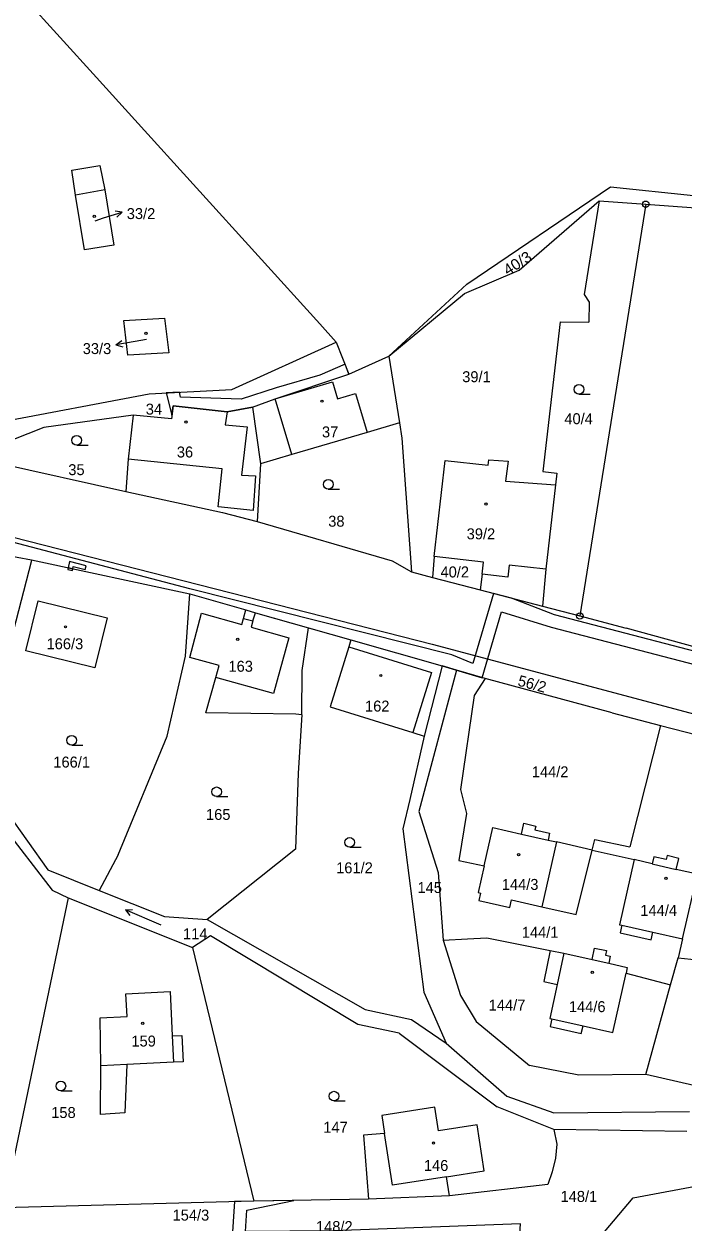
# Model space of a CAD drawing. Extents: x -727701 to -724405, y -960481 to -957284.
# Drawn here: x -726630.1 to -726527.9, y -958207.9 to -958022 of the extents above; entities that cross this region are included whole.
import ezdxf
from ezdxf.enums import TextEntityAlignment as Align

# ---------------------------------------------------------------- set-up
doc = ezdxf.new("R2010")
doc.units = 0
doc.header["$LTSCALE"] = 0.68
for name, color, linetype, lineweight in [('1', 7, 'Continuous', 25), ('13', 7, 'Continuous', 13), ('3', 7, 'Continuous', 25), ('4', 7, 'Continuous', 13), ('5', 7, 'Continuous', 25), ('7', 7, 'Continuous', 13), ('8', 7, 'Continuous', 25)]:
    doc.layers.add(name, color=color, linetype=linetype, lineweight=lineweight)
doc.layers.add('2', color=7, linetype='Continuous')

msp = doc.modelspace()

# ---------------------------------------------------------------- linework, layer by layer
at = {"layer": '1'}
for p, q in [((-726634.18, -958013.37), (-726618.86, -958030.28)), ((-726618.86, -958030.28), (-726612.93, -958036.83)), ((-726612.93, -958036.83), (-726584.21, -958068.52)), ((-726622.71, -958044.65), (-726618.34, -958043.92)), ((-726622.15, -958048.51), (-726622.71, -958044.65)), ((-726618.34, -958043.92), (-726617.58, -958047.72)), ((-726561.41, -958062.33), (-726539.1, -958047.26)), ((-726620.75, -958057.02), (-726622.15, -958048.51)), ((-726617.58, -958047.72), (-726616.18, -958056.3)), ((-726553.27, -958060.18), (-726540.9, -958049.4)), ((-726533.66, -958049.94), (-726543.88, -958113.84)), ((-726540.9, -958049.4), (-726543.21, -958063.93)), ((-726540.9, -958049.4), (-726533.66, -958049.94)), ((-726533.66, -958049.94), (-726525.88, -958050.52)), ((-726616.18, -958056.3), (-726620.75, -958057.02)), ((-726561.79, -958063.8), (-726553.27, -958060.18)), ((-726561.41, -958062.33), (-726573.5, -958073.5)), ((-726573.5, -958073.5), (-726561.79, -958063.8)), ((-726543.21, -958063.93), (-726542.42, -958065.13)), ((-726542.42, -958065.13), (-726542.46, -958068.26)), ((-726614.66, -958067.99), (-726608.33, -958067.64)), ((-726608.33, -958067.64), (-726607.67, -958072.99)), ((-726613.99, -958073.35), (-726614.66, -958067.99)), ((-726581.67, -958071.32), (-726584.21, -958068.52)), ((-726546.92, -958068.2), (-726549.6, -958091.43)), ((-726546.92, -958068.2), (-726542.46, -958068.26)), ((-726597.9, -958078.71), (-726581.67, -958071.32)), ((-726581.67, -958071.32), (-726579.7, -958076.29)), ((-726607.67, -958072.99), (-726613.99, -958073.35)), ((-726579.7, -958076.29), (-726573.5, -958073.5)), ((-726573.5, -958073.5), (-726571.87, -958083.85)), ((-726591.14, -958080.14), (-726579.7, -958076.29)), ((-726610.68, -958079.34), (-726597.9, -958078.71)), ((-726639.17, -958084.77), (-726610.68, -958079.34)), ((-726594.65, -958081.43), (-726591.14, -958080.14)), ((-726613.2, -958082.65), (-726627.07, -958084.61)), ((-726613.2, -958082.65), (-726613.95, -958089.5)), ((-726607.25, -958083.25), (-726613.2, -958082.65)), ((-726607, -958081.25), (-726607.25, -958083.25)), ((-726598.6, -958082.15), (-726607, -958081.25)), ((-726594.65, -958081.43), (-726598.6, -958082.15)), ((-726594.65, -958081.43), (-726593.44, -958090.24)), ((-726571.87, -958083.85), (-726576.9, -958085.34)), ((-726571.87, -958083.85), (-726571.5, -958086.22)), ((-726627.07, -958084.61), (-726638.52, -958089.14)), ((-726576.9, -958085.34), (-726588.57, -958088.8)), ((-726571.5, -958086.22), (-726570, -958107)), ((-726638.52, -958089.14), (-726614.35, -958094.5)), ((-726613.95, -958089.5), (-726614.35, -958094.5)), ((-726588.57, -958088.8), (-726593.44, -958090.24)), ((-726566.5, -958104.6), (-726564.78, -958089.69)), ((-726564.78, -958089.69), (-726558.08, -958090.42)), ((-726558.08, -958090.42), (-726558, -958089.59)), ((-726558, -958089.59), (-726554.99, -958089.84)), ((-726554.99, -958089.84), (-726555.43, -958092.9)), ((-726593.44, -958090.24), (-726593.95, -958099.2)), ((-726549.6, -958091.43), (-726547.46, -958091.68)), ((-726547.46, -958091.68), (-726547.67, -958093.49)), ((-726555.43, -958092.9), (-726547.67, -958093.49)), ((-726547.67, -958093.49), (-726549.17, -958106.58)), ((-726614.35, -958094.5), (-726599.34, -958097.76)), ((-726599.34, -958097.76), (-726593.95, -958099.2)), ((-726593.95, -958099.2), (-726573, -958105.3)), ((-726634.4, -958100.95), (-726566.79, -958118.23)), ((-726633.4, -958104.3), (-726628.95, -958105.15)), ((-726566.5, -958104.6), (-726566.76, -958107.85)), ((-726558.84, -958105.47), (-726566.5, -958104.6)), ((-726628.97, -958105.23), (-726638.69, -958142.79)), ((-726628.95, -958105.15), (-726628.97, -958105.23)), ((-726628.95, -958105.15), (-726604.4, -958110.4)), ((-726573, -958105.3), (-726570, -958107)), ((-726559.06, -958107.36), (-726558.84, -958105.47)), ((-726549.17, -958106.58), (-726549.68, -958112.32)), ((-726570, -958107), (-726566.76, -958107.85)), ((-726566.76, -958107.85), (-726559.35, -958109.79)), ((-726559.06, -958107.36), (-726559.35, -958109.79)), ((-726605.08, -958120.09), (-726604.4, -958110.4)), ((-726604.4, -958110.4), (-726595.69, -958112.91)), ((-726559.35, -958109.79), (-726549.68, -958112.32)), ((-726629.83, -958119.25), (-726627.92, -958111.47)), ((-726627.92, -958111.47), (-726617.22, -958114.13)), ((-726549.68, -958112.32), (-726543.88, -958113.84)), ((-726617.22, -958114.13), (-726619.13, -958121.9)), ((-726604.41, -958120.28), (-726602.58, -958113.43)), ((-726602.58, -958113.43), (-726596.32, -958115.17)), ((-726596.32, -958115.17), (-726596.06, -958114.21)), ((-726596.06, -958114.21), (-726595.69, -958112.91)), ((-726595.69, -958112.91), (-726594.22, -958113.33)), ((-726594.22, -958113.33), (-726586, -958115.7)), ((-726543.88, -958113.84), (-726536.67, -958115.73)), ((-726586.95, -958122.3), (-726586, -958115.7)), ((-726586, -958115.7), (-726579.4, -958117.55)), ((-726492.36, -958127.89), (-726536.67, -958115.73)), ((-726579.4, -958117.55), (-726579.74, -958118.63)), ((-726579.4, -958117.55), (-726565.25, -958121.6)), ((-726619.13, -958121.9), (-726629.83, -958119.25)), ((-726579.74, -958118.63), (-726582.63, -958127.95)), ((-726566.79, -958118.23), (-726443.24, -958151.08)), ((-726607.9, -958132.5), (-726605.08, -958120.09)), ((-726599.86, -958121.55), (-726604.41, -958120.28)), ((-726600.37, -958123.38), (-726599.86, -958121.55)), ((-726565.25, -958121.6), (-726568.02, -958132.48)), ((-726563.01, -958122.26), (-726565.25, -958121.6)), ((-726601.9, -958128.87), (-726600.37, -958123.38)), ((-726587, -958129.2), (-726586.95, -958122.3)), ((-726563.01, -958122.26), (-726568.87, -958144.2)), ((-726558.57, -958123.57), (-726563.01, -958122.26)), ((-726558.57, -958123.57), (-726560.3, -958126.2)), ((-726538.86, -958128.86), (-726558.57, -958123.57)), ((-726560.3, -958126.2), (-726562.42, -958140.75)), ((-726587.95, -958129.08), (-726601.9, -958128.87)), ((-726587, -958129.2), (-726587.95, -958129.08)), ((-726582.63, -958127.95), (-726569.78, -958131.93)), ((-726538.86, -958128.86), (-726531.37, -958130.82)), ((-726587, -958129.2), (-726587.59, -958138.22)), ((-726531.37, -958130.82), (-726536.12, -958149.69)), ((-726531.37, -958130.82), (-726501.37, -958138.64)), ((-726615.5, -958150.9), (-726607.9, -958132.5)), ((-726568.02, -958132.48), (-726570.27, -958142.33)), ((-726569.78, -958131.93), (-726568.02, -958132.48)), ((-726587.59, -958138.22), (-726588.02, -958150.01)), ((-726562.42, -958140.75), (-726561.47, -958144.52)), ((-726570.27, -958142.33), (-726571.34, -958146.9)), ((-726632.73, -958144.34), (-726626.43, -958153.22)), ((-726568.87, -958144.2), (-726565.85, -958153.67)), ((-726561.47, -958144.52), (-726562.67, -958151.79)), ((-726633.59, -958146.25), (-726625.75, -958156.4)), ((-726571.34, -958146.9), (-726568.09, -958172.24)), ((-726558.7, -958152.6), (-726557.36, -958146.69)), ((-726557.36, -958146.69), (-726552.92, -958147.69)), ((-726552.92, -958147.69), (-726552.55, -958146.02)), ((-726552.55, -958146.02), (-726550.72, -958146.48)), ((-726550.72, -958146.48), (-726550.84, -958147.03)), ((-726550.84, -958147.03), (-726548.57, -958147.54)), ((-726548.57, -958147.54), (-726548.81, -958148.62)), ((-726548.81, -958148.62), (-726547.49, -958148.91)), ((-726541.97, -958150.18), (-726547.49, -958148.91)), ((-726541.97, -958150.18), (-726541.53, -958148.52)), ((-726541.53, -958148.52), (-726536.12, -958149.69)), ((-726615.5, -958150.9), (-726618.45, -958156.43)), ((-726588.02, -958150.01), (-726601.69, -958160.96)), ((-726544.46, -958160.19), (-726541.97, -958150.18)), ((-726541.97, -958150.18), (-726535.47, -958151.66)), ((-726532.41, -958151.23), (-726532.66, -958152.31)), ((-726530.49, -958151.64), (-726532.41, -958151.23)), ((-726530.35, -958151.04), (-726530.49, -958151.64)), ((-726528.52, -958151.46), (-726530.35, -958151.04)), ((-726528.91, -958153.17), (-726528.52, -958151.46)), ((-726626.43, -958153.22), (-726618.45, -958156.43)), ((-726562.67, -958151.79), (-726558.7, -958152.6)), ((-726558.7, -958152.6), (-726559.64, -958156.77)), ((-726535.47, -958151.66), (-726537.71, -958161.76)), ((-726532.66, -958152.31), (-726535.47, -958151.66)), ((-726525.61, -958153.92), (-726528.91, -958153.17)), ((-726565.85, -958153.67), (-726565.08, -958164.18)), ((-726527.94, -958163.96), (-726525.61, -958153.92)), ((-726625.75, -958156.4), (-726623.26, -958157.59)), ((-726618.45, -958156.43), (-726608.34, -958160.5)), ((-726559.64, -958156.77), (-726559.3, -958156.85)), ((-726559.3, -958156.85), (-726559.56, -958158.02)), ((-726623.26, -958157.59), (-726633.29, -958205.71)), ((-726623.26, -958157.59), (-726604, -958165.3)), ((-726559.56, -958158.02), (-726554.76, -958159.09)), ((-726554.76, -958159.09), (-726554.5, -958157.92)), ((-726554.5, -958157.92), (-726549.78, -958158.98)), ((-726608.34, -958160.5), (-726601.69, -958160.96)), ((-726549.78, -958158.98), (-726544.46, -958160.19)), ((-726601.69, -958160.96), (-726577.2, -958174.91)), ((-726537.71, -958161.76), (-726537.39, -958161.83)), ((-726537.39, -958161.83), (-726537.65, -958163)), ((-726601.18, -958163.48), (-726604, -958165.3)), ((-726578.31, -958177.24), (-726601.18, -958163.48)), ((-726565.08, -958164.18), (-726561.29, -958163.96)), ((-726565.08, -958164.18), (-726562.42, -958172.76)), ((-726561.29, -958163.96), (-726558.3, -958163.79)), ((-726558.3, -958163.79), (-726548.47, -958165.76)), ((-726537.65, -958163), (-726532.82, -958164.09)), ((-726532.82, -958164.09), (-726532.56, -958162.92)), ((-726532.56, -958162.92), (-726527.94, -958163.96)), ((-726527.94, -958163.96), (-726528.64, -958166.9)), ((-726604, -958165.3), (-726594.48, -958204.65)), ((-726548.47, -958165.76), (-726549.47, -958170.59)), ((-726548.47, -958165.76), (-726546.37, -958166.18)), ((-726546.37, -958166.18), (-726541.98, -958167.16)), ((-726541.98, -958167.16), (-726541.59, -958165.4)), ((-726541.59, -958165.4), (-726539.74, -958165.74)), ((-726539.74, -958165.74), (-726539.91, -958166.49)), ((-726539.91, -958166.49), (-726539.15, -958166.66)), ((-726539.15, -958166.66), (-726539.39, -958167.74)), ((-726539.39, -958167.74), (-726536.52, -958168.39)), ((-726529.79, -958171.09), (-726528.64, -958166.9)), ((-726528.64, -958166.9), (-726508.31, -958169.06)), ((-726538.77, -958178.46), (-726536.71, -958169.26)), ((-726536.52, -958168.39), (-726536.71, -958169.26)), ((-726536.71, -958169.26), (-726529.79, -958171.09)), ((-726549.47, -958170.59), (-726547.42, -958171.01)), ((-726547.42, -958171.01), (-726548.56, -958176.3)), ((-726533.62, -958184.99), (-726529.79, -958171.09)), ((-726614.3, -958172.47), (-726607.45, -958172.13)), ((-726614.12, -958176.01), (-726614.3, -958172.47)), ((-726607.45, -958172.13), (-726607.11, -958179.01)), ((-726568.09, -958172.24), (-726564.61, -958180.15)), ((-726562.42, -958172.76), (-726559.95, -958176.78)), ((-726577.2, -958174.91), (-726569.99, -958176.49)), ((-726618.32, -958176.21), (-726614.12, -958176.01)), ((-726618.21, -958183.67), (-726618.32, -958176.21)), ((-726571.9, -958178.57), (-726578.31, -958177.24)), ((-726569.99, -958176.49), (-726564.61, -958180.15)), ((-726559.95, -958176.78), (-726551.71, -958183.62)), ((-726548.56, -958176.3), (-726548.22, -958176.38)), ((-726548.22, -958176.38), (-726548.48, -958177.55)), ((-726543.65, -958178.62), (-726543.39, -958177.44)), ((-726543.39, -958177.44), (-726538.77, -958178.46)), ((-726607.11, -958179.01), (-726605.61, -958178.94)), ((-726605.61, -958178.94), (-726605.41, -958183.04)), ((-726571.9, -958178.57), (-726556.73, -958190.04)), ((-726548.48, -958177.55), (-726543.65, -958178.62)), ((-726564.61, -958180.15), (-726555.22, -958188.35)), ((-726605.41, -958183.04), (-726606.91, -958183.11)), ((-726618.24, -958191.21), (-726618.21, -958183.67)), ((-726614.15, -958183.47), (-726614.46, -958190.94)), ((-726606.91, -958183.11), (-726614.15, -958183.47)), ((-726544.02, -958185.11), (-726551.71, -958183.62)), ((-726533.62, -958184.99), (-726544.02, -958185.11)), ((-726513.25, -958189.75), (-726533.62, -958184.99)), ((-726555.22, -958188.35), (-726547.93, -958190.97)), ((-726566.36, -958190.07), (-726574.62, -958191.36)), ((-726565.79, -958193.75), (-726566.36, -958190.07)), ((-726547.92, -958193.53), (-726556.73, -958190.04)), ((-726614.46, -958190.94), (-726618.24, -958191.21)), ((-726574.62, -958191.36), (-726574.18, -958194.18)), ((-726547.93, -958190.97), (-726526.87, -958190.73)), ((-726574.18, -958194.18), (-726577.45, -958194.43)), ((-726559.81, -958192.82), (-726565.79, -958193.75)), ((-726558.7, -958199.97), (-726559.81, -958192.82)), ((-726527.26, -958193.85), (-726547.92, -958193.53)), ((-726547.92, -958193.53), (-726547.44, -958195.8)), ((-726577.45, -958194.43), (-726576.69, -958204.35)), ((-726547.44, -958195.8), (-726547.68, -958197.99)), ((-726547.68, -958197.99), (-726548.17, -958200.1)), ((-726564.58, -958200.88), (-726558.7, -958199.97)), ((-726564.13, -958203.82), (-726564.58, -958200.88)), ((-726548.17, -958200.1), (-726548.85, -958202.09)), ((-726548.85, -958202.09), (-726564.13, -958203.82)), ((-726535.63, -958204.12), (-726524.27, -958202)), ((-726594.48, -958204.65), (-726633.29, -958205.71)), ((-726576.69, -958204.35), (-726594.48, -958204.65)), ((-726564.13, -958203.82), (-726576.69, -958204.35)), ((-726544.56, -958214.79), (-726535.63, -958204.12))]:
    msp.add_line(p, q, dxfattribs=at)
msp.add_lwpolyline([(-726539.1, -958047.26), (-726526.27, -958048.56), (-726525.88, -958050.52), (-726524.67, -958051.03)], dxfattribs=at)
at = {"layer": '13'}
for points in [[(-726580.31, -958074.76), (-726584.24, -958076.45), (-726591.01, -958078.41), (-726596.45, -958080.2), (-726605.82, -958079.88), (-726606.02, -958079.11), (-726608.05, -958079.21), (-726607.18, -958082.69), (-726607, -958081.25), (-726598.6, -958082.15), (-726594.65, -958081.43), (-726591.14, -958080.14), (-726579.7, -958076.29)], [(-726623.3, -958106.61), (-726622.62, -958106.76), (-726622.56, -958106.52), (-726623.25, -958106.37)], [(-726623.25, -958106.37), (-726622.56, -958106.52), (-726622.48, -958106.17), (-726620.65, -958106.63), (-726620.5, -958106.05), (-726623.04, -958105.41)], [(-726594.48, -958204.65), (-726597.46, -958204.73), (-726597.89, -958210.97), (-726587.7, -958210.7), (-726587.45, -958211.3), (-726583.72, -958211.27), (-726580.73, -958213.13), (-726579.4, -958213.15), (-726579.42, -958211.16), (-726555.25, -958210.25), (-726555.32, -958211.34), (-726553.3, -958211.15), (-726553.11, -958208.16), (-726582.05, -958209.26), (-726595.78, -958209.36), (-726595.55, -958206.05), (-726588.27, -958204.55)]]:
    msp.add_lwpolyline(points, close=True, dxfattribs=at)
for points in [[(-726486.7, -958129.58), (-726547.8, -958113.68), (-726554.49, -958111.06), (-726557.27, -958110.33), (-726560.49, -958121.2), (-726563.75, -958119.85), (-726604.4, -958109.65), (-726644.73, -958099.04)], [(-726633.4, -958104.3), (-726628.95, -958105.15), (-726604.4, -958110.4), (-726595.69, -958112.91), (-726594.22, -958113.33), (-726579.4, -958117.55), (-726565.25, -958121.6), (-726559.06, -958123.43), (-726556.03, -958113.19), (-726548.35, -958115.6), (-726487.36, -958131.48)]]:
    msp.add_lwpolyline(points, dxfattribs=at)
at = {"layer": '3'}
for p, q in [((-726544.013, -958079.42), (-726542.263, -958079.42)), ((-726621.943, -958087.33), (-726620.193, -958087.33)), ((-726582.913, -958094.16), (-726581.163, -958094.16)), ((-726622.723, -958133.88), (-726620.973, -958133.88)), ((-726600.233, -958141.88), (-726598.483, -958141.88)), ((-726579.583, -958149.74), (-726577.833, -958149.74)), ((-726614.384, -958159.473), (-726613.289, -958159.393)), ((-726624.403, -958187.54), (-726622.653, -958187.54)), ((-726582.033, -958189.11), (-726580.283, -958189.11))]:
    msp.add_line(p, q, dxfattribs=at)
msp.add_lwpolyline([(-726608.861, -958161.818), (-726614.384, -958159.473), (-726613.68, -958160.317)], dxfattribs=at)
for centre in [(-726544.0129, -958078.6698), (-726621.9429, -958086.5798), (-726582.9129, -958093.4098), (-726622.7229, -958133.1298), (-726600.2329, -958141.1298), (-726579.5829, -958148.9898), (-726624.4029, -958186.7898), (-726582.0329, -958188.3598)]:
    msp.add_circle(centre, 0.75, dxfattribs=at)
at = {"layer": '4'}
for p, q in [((-726617.58, -958047.72), (-726622.15, -958048.51)), ((-726591.14, -958080.14), (-726582.25, -958077.51)), ((-726582.25, -958077.51), (-726581.46, -958080.16)), ((-726588.57, -958088.8), (-726591.14, -958080.14)), ((-726581.46, -958080.16), (-726578.68, -958079.33)), ((-726578.68, -958079.33), (-726576.9, -958085.34)), ((-726598.6, -958082.15), (-726598.9, -958084.15)), ((-726598.9, -958084.15), (-726595.5, -958084.5)), ((-726595.5, -958084.5), (-726596.4, -958092)), ((-726599.4, -958091), (-726613.95, -958089.5)), ((-726600, -958096.9), (-726599.4, -958091)), ((-726596.4, -958092), (-726594.22, -958092.1)), ((-726594.22, -958092.1), (-726594.55, -958097.45)), ((-726594.55, -958097.45), (-726600, -958096.9)), ((-726554.84, -958105.93), (-726555.05, -958107.82)), ((-726549.17, -958106.58), (-726554.84, -958105.93)), ((-726555.05, -958107.82), (-726559.06, -958107.36)), ((-726596.06, -958114.21), (-726594.61, -958114.61)), ((-726594.61, -958114.61), (-726594.22, -958113.33)), ((-726594.61, -958114.61), (-726594.88, -958115.57)), ((-726594.88, -958115.57), (-726589.01, -958117.21)), ((-726589.01, -958117.21), (-726591.42, -958125.87)), ((-726579.74, -958118.63), (-726566.89, -958122.62)), ((-726591.42, -958125.87), (-726600.37, -958123.38)), ((-726566.89, -958122.62), (-726569.78, -958131.93)), ((-726552.92, -958147.69), (-726548.81, -958148.62)), ((-726547.49, -958148.91), (-726549.78, -958158.98)), ((-726532.66, -958152.31), (-726528.91, -958153.17)), ((-726537.39, -958161.83), (-726532.56, -958162.92)), ((-726546.37, -958166.18), (-726547.42, -958171.01)), ((-726541.98, -958167.16), (-726539.39, -958167.74)), ((-726548.22, -958176.38), (-726543.39, -958177.44)), ((-726607.11, -958179.01), (-726606.91, -958183.11)), ((-726614.15, -958183.47), (-726618.21, -958183.67)), ((-726572.94, -958202.18), (-726574.18, -958194.18)), ((-726564.58, -958200.88), (-726572.94, -958202.18))]:
    msp.add_line(p, q, dxfattribs=at)
at = {"layer": '5'}
for centre in [(-726619.2268, -958051.8292), (-726611.2068, -958069.9692), (-726583.8968, -958080.4992), (-726605.0068, -958083.7392), (-726558.4468, -958096.4692), (-726623.6868, -958115.5292), (-726596.9668, -958117.4492), (-726574.7568, -958123.0792), (-726553.3868, -958150.8692), (-726530.5168, -958154.5492), (-726541.9568, -958169.1592), (-726611.6968, -958177.0692), (-726566.5868, -958195.6392)]:
    msp.add_circle(centre, 0.175, dxfattribs=at)
at = {"layer": '7'}
for p, q in [((-726614.9, -958051.193), (-726616.004, -958051.007)), ((-726615.855, -958071.771), (-726614.782, -958072.09))]:
    msp.add_line(p, q, dxfattribs=at)
for points in [[(-726619.1, -958052.49), (-726617.77, -958052.07), (-726614.9, -958051.193), (-726615.711, -958051.964)], [(-726611.1, -958070.92), (-726612.9, -958071.25), (-726615.855, -958071.771), (-726614.956, -958071.104)]]:
    msp.add_lwpolyline(points, dxfattribs=at)
at = {"layer": '8'}
for centre, radius in [((-726533.66, -958049.9399), 0.5), ((-726533.66, -958049.9399), 0.0303), ((-726543.88, -958113.8399), 0.5), ((-726543.88, -958113.8399), 0.0303)]:
    msp.add_circle(centre, radius, dxfattribs=at)

# ---------------------------------------------------------------- texts
at = {"layer": '2'}
for s, p in [('33/2', (-726614.18, -958052.242)), ('34', (-726611.23, -958082.585)), ('37', (-726583.89, -958086.125)), ('36', (-726606.41, -958089.245)), ('35', (-726623.25, -958091.985)), ('38', (-726582.92, -958099.985)), ('39/2', (-726561.44, -958101.945)), ('40/2', (-726565.5, -958107.855)), ('163', (-726598.4, -958122.495)), ('162', (-726577.21, -958128.675)), ('165', (-726601.88, -958145.495)), ('161/2', (-726581.69, -958153.775)), ('145', (-726569.07, -958156.835)), ('144/3', (-726555.99, -958156.355)), ('144/4', (-726534.49, -958160.385)), ('114', (-726605.45, -958164.015)), ('144/6', (-726545.58, -958175.325)), ('159', (-726613.46, -958180.665)), ('158', (-726625.9, -958191.755)), ('147', (-726583.68, -958194.035)), ('146', (-726568.08, -958199.975))]:
    msp.add_text(s, height=1.7, dxfattribs=at).set_placement(p)
at = {"layer": '2', "width": 1.05}
msp.add_text('40/3', height=1.7, rotation=33, dxfattribs=at).set_placement((-726555.058, -958061.056))
at = {"layer": '2'}
msp.add_text('33/3', height=1.7, dxfattribs=at).set_placement((-726616.589, -958073.192), align=Align.RIGHT)
for s, p in [('39/1', (-726559.919, -958077.555)), ('40/4', (-726544.069, -958084.075)), ('166/3', (-726623.78, -958119.005)), ('166/1', (-726622.73, -958137.365)), ('144/2', (-726548.49, -958138.875)), ('144/1', (-726550.04, -958163.785)), ('144/7', (-726555.18, -958175.085)), ('148/1', (-726544.03, -958204.775)), ('154/3', (-726604.23, -958207.675)), ('148/2', (-726581.98, -958209.455))]:
    msp.add_text(s, height=1.7, dxfattribs=at).set_placement(p, align=Align.CENTER)
msp.add_text('56/2', height=1.7, rotation=345, dxfattribs=at).set_placement((-726551.497, -958125.2), align=Align.CENTER)

doc.saveas('drawing.dxf')
